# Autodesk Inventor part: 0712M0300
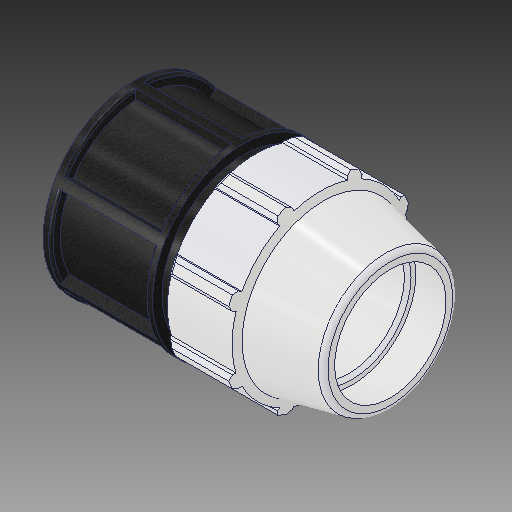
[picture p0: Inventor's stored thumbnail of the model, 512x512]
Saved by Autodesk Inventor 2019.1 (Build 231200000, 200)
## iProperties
Created: 2017-02
Part Number: 0712M0300
Material: PVC-Piping
Description: PLASSON END PLUG 3''
Document SubType Name: Modeling
Designer: KIM
Mass: 92.6774 g
Surface Area: 199.44 cm^2
Volume: 66.1981 cm^3
Density: 1.4 g/cm^3
Appearance: PTFE
Author: Кирилл
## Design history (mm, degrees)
derived "0712M0.ipt"
feature "Solid1::0712M0.ipt"
tag "TaggingFeature1"
body "Solid1"
other parameters: "d2" = 88.7, "d4" = 30.55257, "d5" = 53.467, "d7" = 151.892, "d8" = 129.1082, "d9" = 30.55257, "d11" = 6.11051, "d12" = 129.1082, "d13" = 120 deg, "d15" = 12 deg, "d16" = 144.2974, "d18" = 4.435, "d19" = 35 deg, "d20" = 17.5 deg, "d21" = 141.25956, "d23" = 0, "d25" = 360 deg, "d27" = 3.03784, "d34" = 7.5946, "d36" = 0, "d42" = 53.467, "d43" = 4.55676, "d46" = 2.661, "d53" = 1.774, "d55" = 360 deg, "d59" = 74.8538, "d64" = 213.868, "d66" = 15.1892, "d67" = 7.5946, "d68" = 198.12, "d70" = 129.1082, "d_" = 88.7, "E_" = 151.892, "H_" = 213.868, "l_" = 198.12
